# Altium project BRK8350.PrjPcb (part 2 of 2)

## Sheet Transceiver-M2.SchDoc: BRK8350 - M.2
size C; Author: Casey Smith; Organization: Opal Kelly; Address1: 13500 SW 72nd Ave STE 100; Address2: Portland, OR 97223; Address3: 217.391.3724; Address4: http://www.opalkelly.com; DocumentNumber: xxx; Revision: 1; SheetNumber: 6; SheetTotal: 7
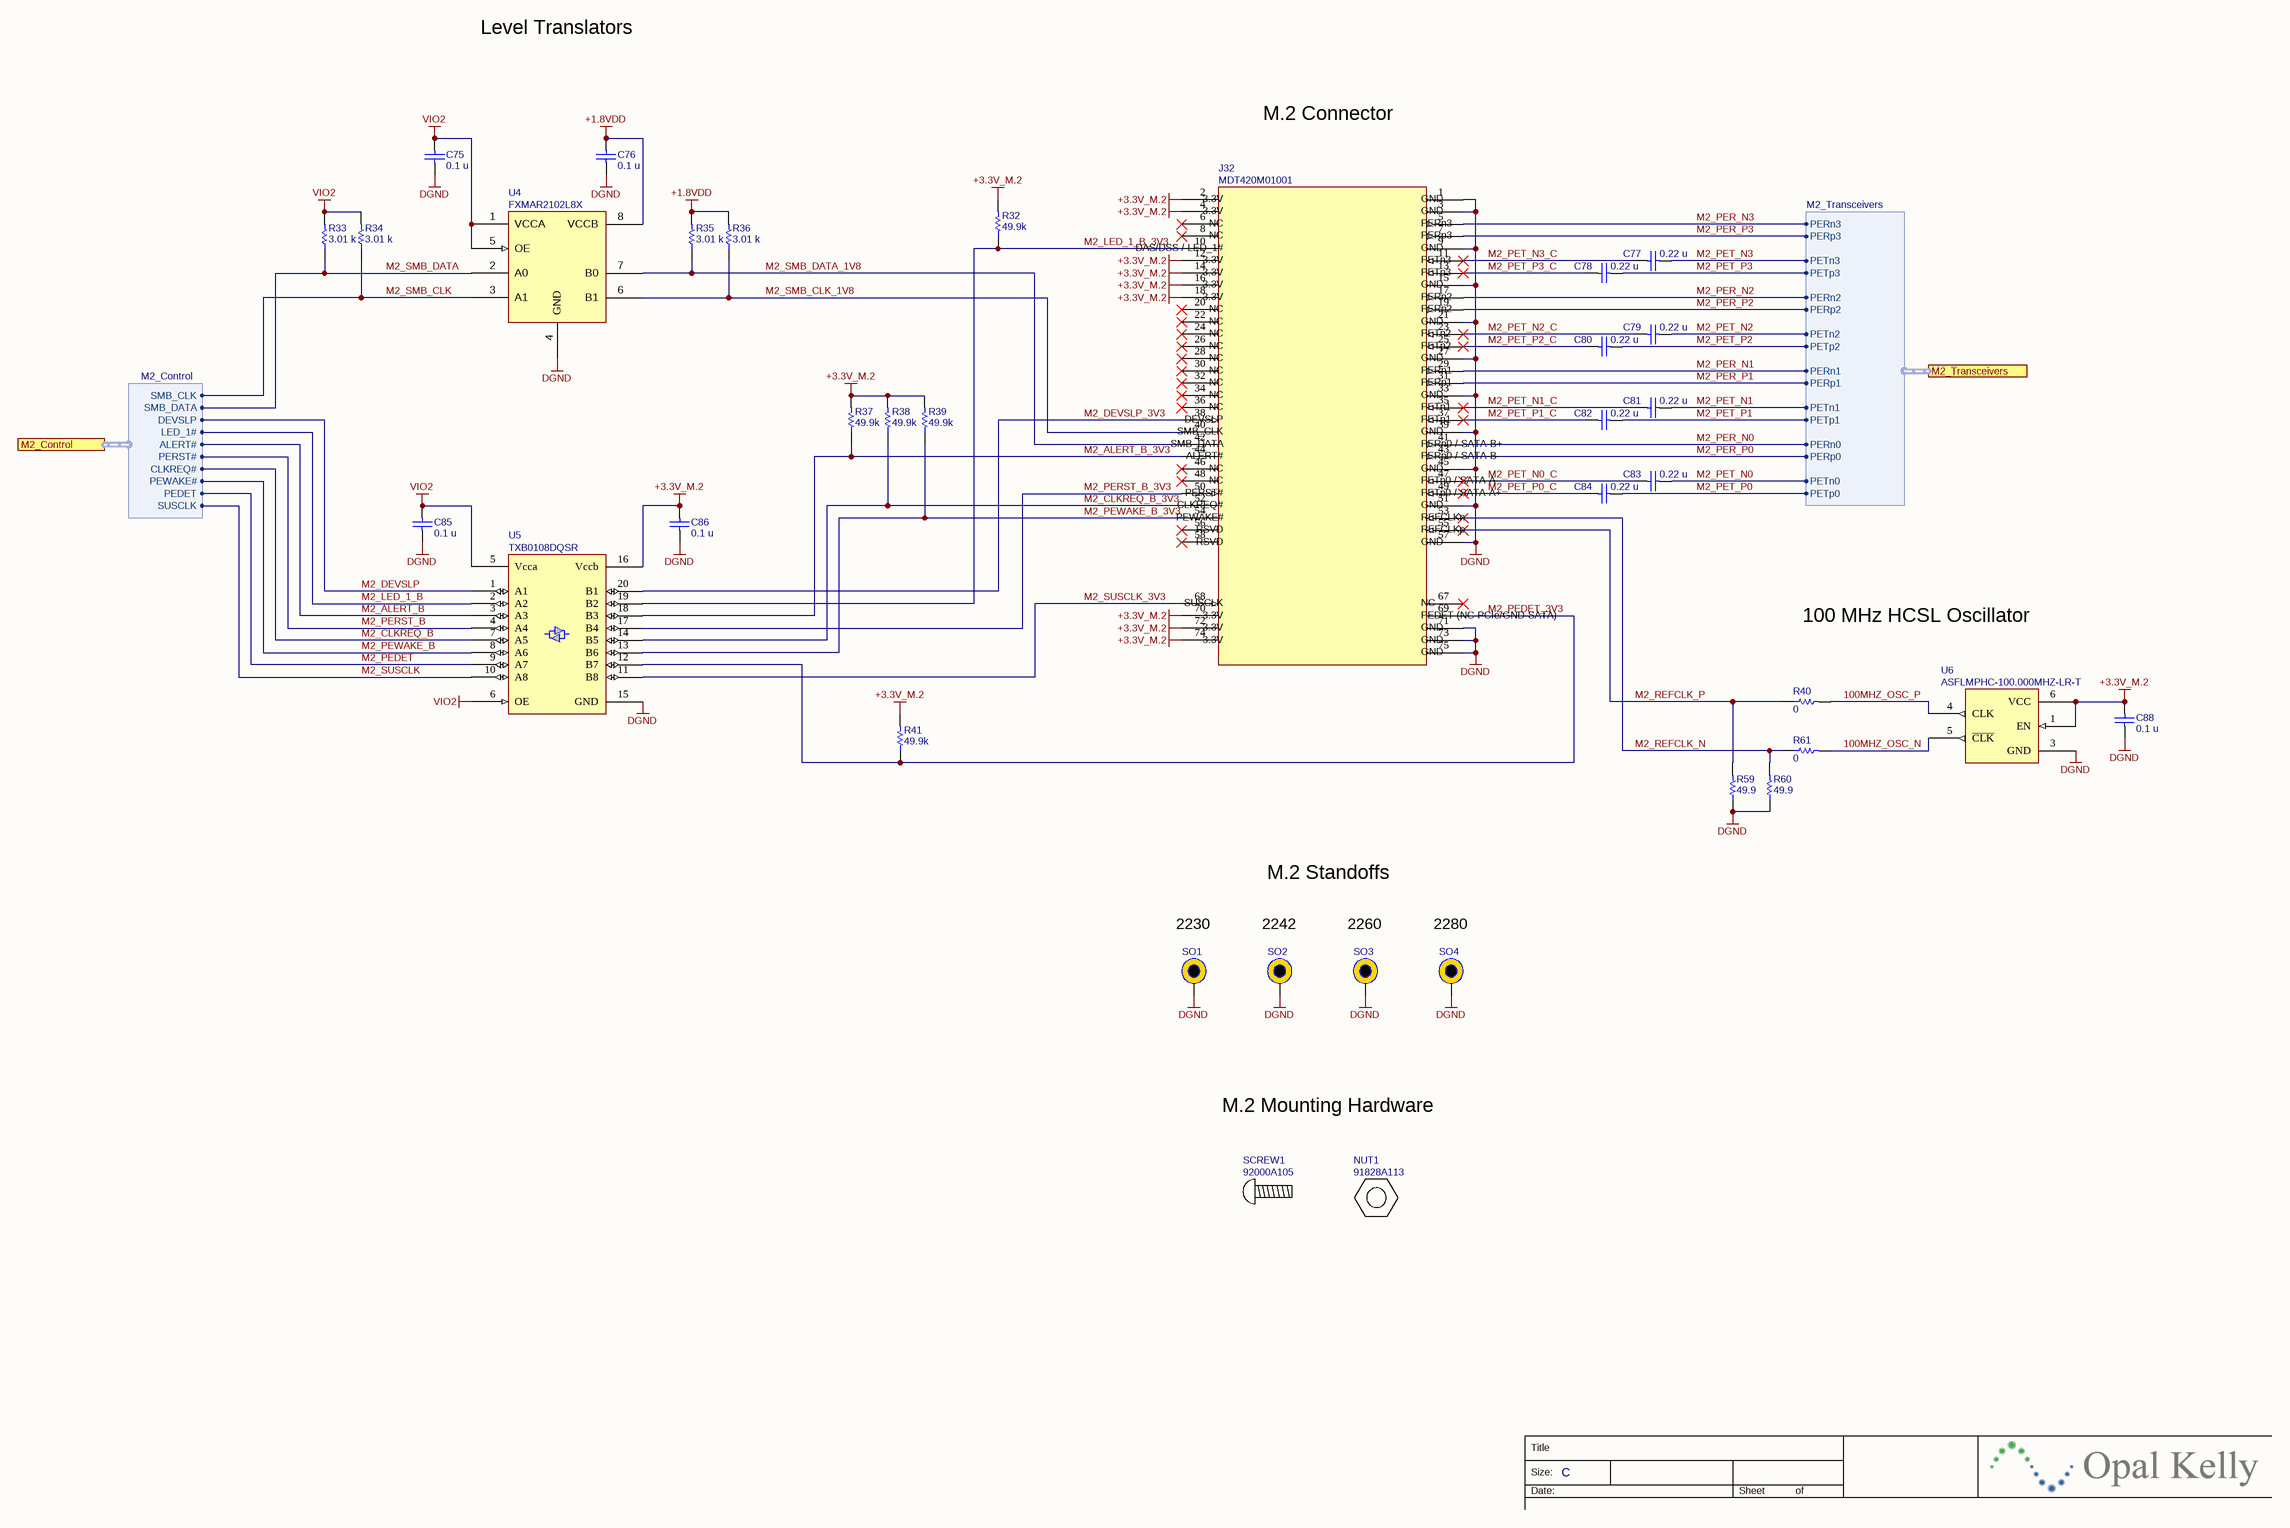
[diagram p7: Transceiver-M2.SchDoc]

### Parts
C75  value 0.1 u  [CAPC1005X06A]  (hidden comment: SM-0402, 10%, 10v)
C76  value 0.1 u  [CAPC1005X06A]  (hidden comment: SM-0402, 10%, 10v)
C77  value 0.22 u  [CAPC1005X06A]  (hidden comment: SM-0402, 10%, 10V, X5R)
C78  value 0.22 u  [CAPC1005X06A]  (hidden comment: SM-0402, 10%, 10V, X5R)
C79  value 0.22 u  [CAPC1005X06A]  (hidden comment: SM-0402, 10%, 10V, X5R)
C80  value 0.22 u  [CAPC1005X06A]  (hidden comment: SM-0402, 10%, 10V, X5R)
C81  value 0.22 u  [CAPC1005X06A]  (hidden comment: SM-0402, 10%, 10V, X5R)
C82  value 0.22 u  [CAPC1005X06A]  (hidden comment: SM-0402, 10%, 10V, X5R)
C83  value 0.22 u  [CAPC1005X06A]  (hidden comment: SM-0402, 10%, 10V, X5R)
C84  value 0.22 u  [CAPC1005X06A]  (hidden comment: SM-0402, 10%, 10V, X5R)
C85  value 0.1 u  [CAPC1005X06A]  (hidden comment: SM-0402, 10%, 10v)
C86  value 0.1 u  [CAPC1005X06A]  (hidden comment: SM-0402, 10%, 10v)
C88  value 0.1 u  [CAPC1005X06A]  (hidden comment: SM-0402, 10%, 10v)
J32  MDT420M01001  [M2-Connector_M-Keying]
NUT1  91828A113  (mechanical)
R32  value 49.9k  [RESC1005X06A]  (hidden comment: SM-0402, 1%, 1/16W)
R33  value 3.01 k  [RESC1005X06A]  (hidden comment: SM-0402, 1%, 1/16W)
R34  value 3.01 k  [RESC1005X06A]  (hidden comment: SM-0402, 1%, 1/16W)
R35  value 3.01 k  [RESC1005X06A]  (hidden comment: SM-0402, 1%, 1/16W)
R36  value 3.01 k  [RESC1005X06A]  (hidden comment: SM-0402, 1%, 1/16W)
R37  value 49.9k  [RESC1005X06A]  (hidden comment: SM-0402, 1%, 1/16W)
R38  value 49.9k  [RESC1005X06A]  (hidden comment: SM-0402, 1%, 1/16W)
R39  value 49.9k  [RESC1005X06A]  (hidden comment: SM-0402, 1%, 1/16W)
R40  value 0  [RESC1005X06A]  (hidden comment: SM-0402, 1%, 1/16W)
R41  value 49.9k  [RESC1005X06A]  (hidden comment: SM-0402, 1%, 1/16W)
R59  value 49.9  [RESC1005X06A]  (hidden comment: SM-0402, 1%, 1/16W)
R60  value 49.9  [RESC1005X06A]  (hidden comment: SM-0402, 1%, 1/16W)
R61  value 0  [RESC1005X06A]  (hidden comment: SM-0402, 1%, 1/16W)
SCREW1  92000A105  (mechanical)
SO1  Standoff  [9774025151R-NO-PASTE]  (value not drawn)
SO2  Standoff  [9774025151R-NO-PASTE]  (value not drawn)
SO3  Standoff  [9774025151R-NO-PASTE]  (value not drawn)
SO4  Standoff  [9774025151R-NO-PASTE]  (value not drawn)
U4  FXMAR2102L8X  [FXMAR2102L8X]
U5  TXB0108DQSR  [TXB0108DQSR]
U6  ASFLMPHC-100.000MHZ-LR-T  [OSC_SMD_5x32]

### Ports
M2_Control (harness M2_Control), M2_Transceivers (harness M2_Transceivers)

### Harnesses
M2_Control: DEVSLP, SMB_CLK, SMB_DATA, ALERT#, PERST#, CLKREQ#, PEWAKE#, LED_1#, SUSCLK, PEDET
M2_Transceivers: PETn3, PETp3, PERn3, PERp3, PETn2, PETp2, PERn2, PERp2, PETn1, PETp1, PERn1, PERp1, PETn0, PETp0, PERn0, PERp0

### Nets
+1.8VDD: C76.2 R35.2 R36.2 U4.8(VCCB)
+3.3V_M.2: C86.2 C88.2 J32.2 J32.4 J32.12 J32.14 J32.16 J32.18 J32.70 J32.72 J32.74 R32.2 R37.2 R38.2 R39.2 R41.2 U5.16(Vccb) U6.1(EN) U6.6(VCC)
DGND: C75.1 C76.1 C85.1 C86.1 C88.1 J32.1 J32.3 J32.9 J32.15 J32.21 J32.27 J32.33 J32.39 J32.45 J32.51 J32.57 J32.71 J32.73 J32.75 R59.1 R60.1 SO1.1 SO2.1 SO3.1 SO4.1 U4.4(GND) U5.15(GND) U6.3(GND)
VIO2: C75.2 C85.2 R33.2 R34.2 U4.1(VCCA) U4.5(OE) U5.5(Vcca) U5.6(OE)
100MHZ_OSC_N: R61.2 U6.5(~{CLK})
100MHZ_OSC_P: R40.2 U6.4(CLK)
M2_ALERT_B: U5.3(A3) ; port M2_Control.ALERT#
M2_ALERT_B_3V3: J32.44 R37.1 U5.18(B3)
M2_CLKREQ_B: U5.7(A5) ; port M2_Control.CLKREQ#
M2_CLKREQ_B_3V3: J32.52 R38.1 U5.14(B5)
M2_DEVSLP: U5.1(A1) ; port M2_Control.DEVSLP
M2_DEVSLP_3V3: J32.38 U5.20(B1)
M2_LED_1_B: U5.2(A2) ; port M2_Control.LED_1#
M2_LED_1_B_3V3: J32.10 R32.1 U5.19(B2)
M2_PEDET: U5.9(A7) ; port M2_Control.PEDET
M2_PEDET_3V3: J32.69 R41.1 U5.12(B7)
M2_PER_N0: J32.41 ; port M2_Transceivers.PERn0
M2_PER_N1: J32.29 ; port M2_Transceivers.PERn1
M2_PER_N2: J32.17 ; port M2_Transceivers.PERn2
M2_PER_N3: J32.5 ; port M2_Transceivers.PERn3
M2_PER_P0: J32.43 ; port M2_Transceivers.PERp0
M2_PER_P1: J32.31 ; port M2_Transceivers.PERp1
M2_PER_P2: J32.19 ; port M2_Transceivers.PERp2
M2_PER_P3: J32.7 ; port M2_Transceivers.PERp3
M2_PERST_B: U5.4(A4) ; port M2_Control.PERST#
M2_PERST_B_3V3: J32.50 U5.17(B4)
M2_PET_N0: C83.1 ; port M2_Transceivers.PETn0
M2_PET_N0_C: C83.2 J32.47
M2_PET_N1: C81.1 ; port M2_Transceivers.PETn1
M2_PET_N1_C: C81.2 J32.35
M2_PET_N2: C79.1 ; port M2_Transceivers.PETn2
M2_PET_N2_C: C79.2 J32.23
M2_PET_N3: C77.1 ; port M2_Transceivers.PETn3
M2_PET_N3_C: C77.2 J32.11
M2_PET_P0: C84.1 ; port M2_Transceivers.PETp0
M2_PET_P0_C: C84.2 J32.49
M2_PET_P1: C82.1 ; port M2_Transceivers.PETp1
M2_PET_P1_C: C82.2 J32.37
M2_PET_P2: C80.1 ; port M2_Transceivers.PETp2
M2_PET_P2_C: C80.2 J32.25
M2_PET_P3: C78.1 ; port M2_Transceivers.PETp3
M2_PET_P3_C: C78.2 J32.13
M2_PEWAKE_B: U5.8(A6) ; port M2_Control.PEWAKE#
M2_PEWAKE_B_3V3: J32.54 R39.1 U5.13(B6)
M2_REFCLK_N: J32.53 R60.2 R61.1
M2_REFCLK_P: J32.55 R40.1 R59.2
M2_SMB_CLK: R34.1 U4.3(A1) ; port M2_Control.SMB_CLK
M2_SMB_CLK_1V8: J32.40 R36.1 U4.6(B1)
M2_SMB_DATA: R33.1 U4.2(A0) ; port M2_Control.SMB_DATA
M2_SMB_DATA_1V8: J32.42 R35.1 U4.7(B0)
M2_SUSCLK: U5.10(A8) ; port M2_Control.SUSCLK
M2_SUSCLK_3V3: J32.68 U5.11(B8)

Not connected (* = marked no-connect by the designer): J32 6* 8* 20* 22* 24* 26* 28* 30* 32* 34* 36* 46* 48* 56* 58* 67*

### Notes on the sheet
- Level Translators
- M.2 Connector
- 100 MHz HCSL Oscillator
- M.2 Standoffs
- 2230
- 2242
- 2260
- 2280
- M.2 Mounting Hardware
- Title
- Size:
- Date:
- C
- Sheet
- of

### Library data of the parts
C75 C76 C85 C86 C88 = 000070: Partnumber: 000070; manufacturer: Kemet; manufacturer_pn: C0402C104K8PACTU; ValueFloat: 1E-7; id: 750; inventory_price: 0.0023; reorder_quantity: 70000; x_tolerance: 10
C77-C84 = 000333: Partnumber: 000333; manufacturer: Taiyo Yuden; manufacturer_pn: LMK105BJ224KV-F; ValueFloat: 2.2E-7; id: 3750; inventory_price: 0.0056; reorder_quantity: 10000; x_tolerance: 10
J32 = 001722: Partnumber: 001722; manufacturer: Amphenol; id: 221876; inventory_price: 0.75
NUT1 = NUT: M2.5 hex nut; Manufacturer: McMaster-Carr; partnumber: 001810
R32 R37-R39 R41 = 001035: Partnumber: 001035; manufacturer: Vishay; manufacturer_pn: CRCW040249K9FKED; ValueFloat: 49900; id: 26623; inventory_price: 0.0015; x_tolerance: 1
R33-R36 = 001126: Partnumber: 001126; manufacturer: Vishay; manufacturer_pn: CRCW04023K01FKED; ValueFloat: 3010; id: 35682; inventory_price: 0.015; x_tolerance: 1
R40 R61 = 001713: Partnumber: 001713; manufacturer: Vishay; manufacturer_pn: CRCW04020000Z0EDC; id: 219362; inventory_price: 0.004; reorder_quantity: 20000; x_tolerance: 1
R59 R60 = 001715: Partnumber: 001715; manufacturer: Vishay; manufacturer_pn: CRCW040249R9FKEDC; id: 219364; inventory_price: 0.005; reorder_quantity: 1000; x_tolerance: 1
SCREW1 = SCREW: Metric Pan Head Phil Machine Screw; Manufacturer: McMaster-Carr; partnumber: 001811
SO1-SO4 = 9774025151R: SMT steel standoff, M2.5 threads, 2.5 mm stack height; Manufacturer: Wurth; partnumber: 001726
U4 = 001559: Partnumber: 001559; manufacturer: ON Semiconductor; id: 168047; inventory_price: 0.3
U5 = 001324: Partnumber: 001324; manufacturer: Texas Instruments; id: 94563; inventory_price: 1.67
U6 = 001804: Partnumber: 001804; manufacturer: Abracon; id: 273756; inventory_price: 2.65

## Sheet MC3-Transceiver.SchDoc: BRK8350 - Mezzanine Connector MC3
size C; Author: Casey Smith; Organization: Opal Kelly; Address1: 13500 SW 72nd Ave STE 100; Address2: Portland, OR 97223; Address3: 217.391.3724; Address4: http://www.opalkelly.com; DocumentNumber: xxx; Revision: 1; SheetNumber: 4; SheetTotal: 7
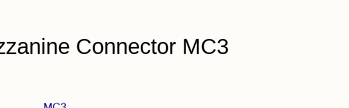
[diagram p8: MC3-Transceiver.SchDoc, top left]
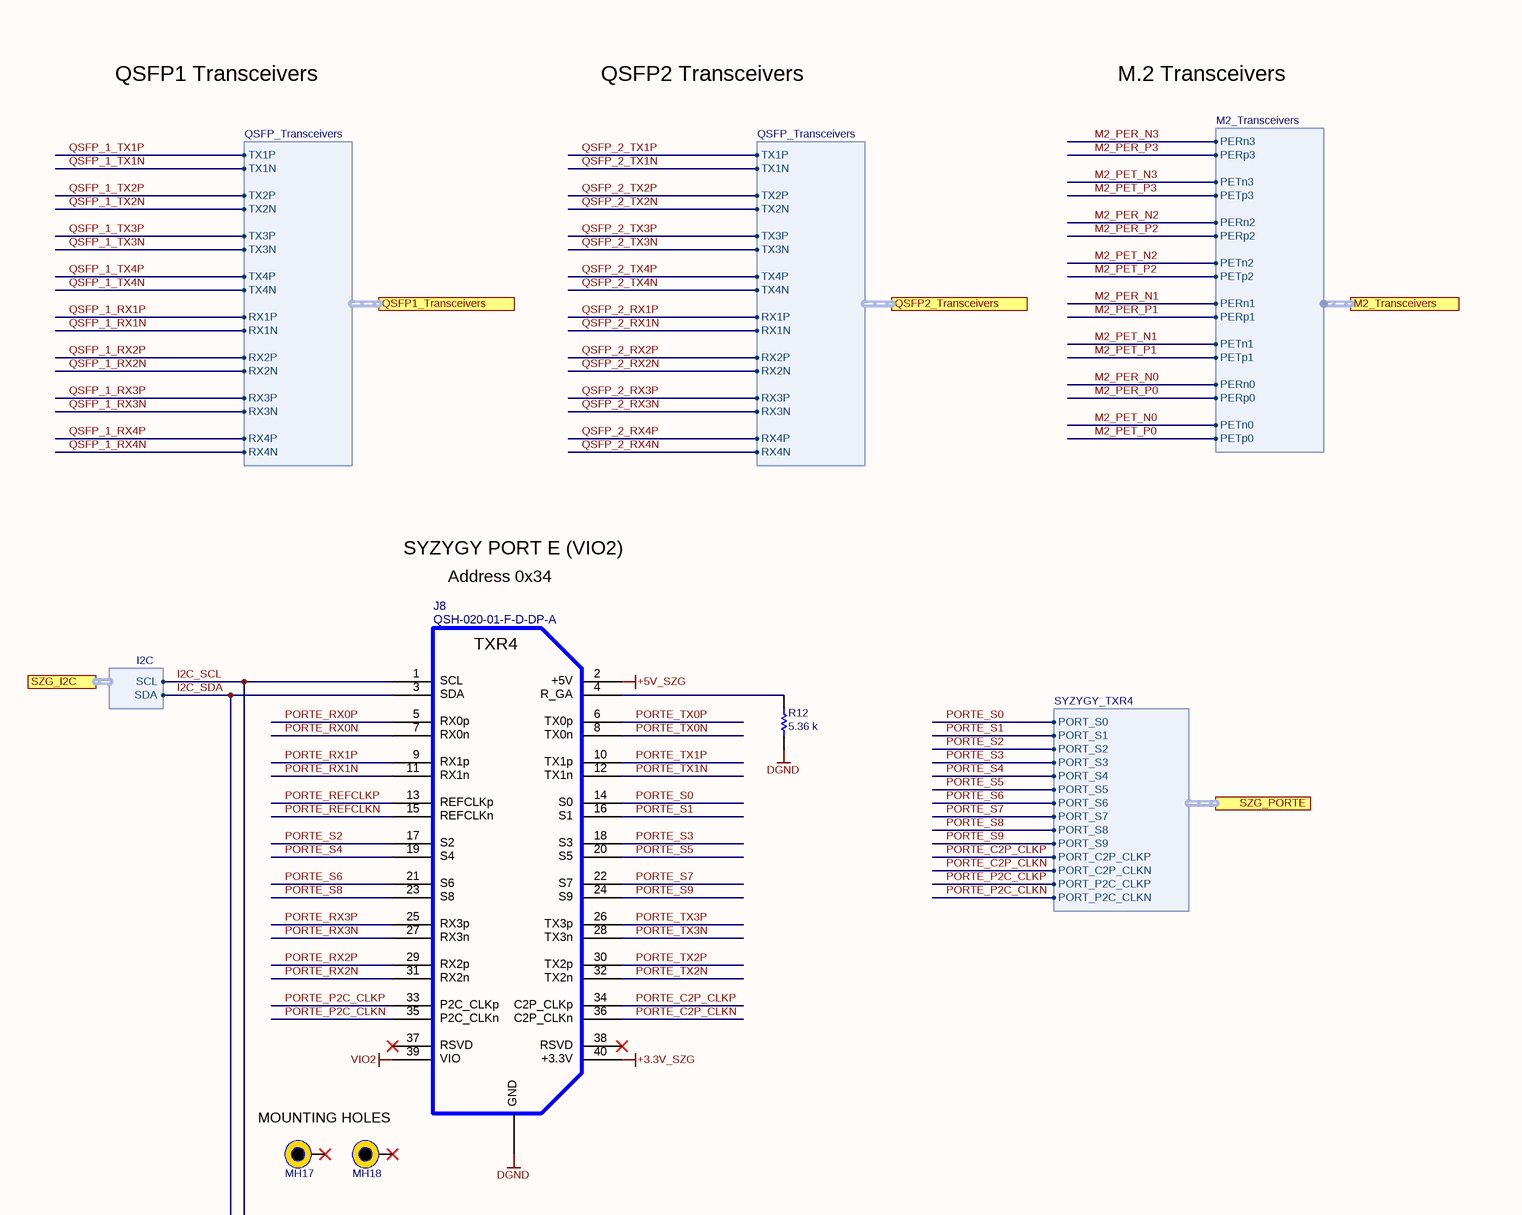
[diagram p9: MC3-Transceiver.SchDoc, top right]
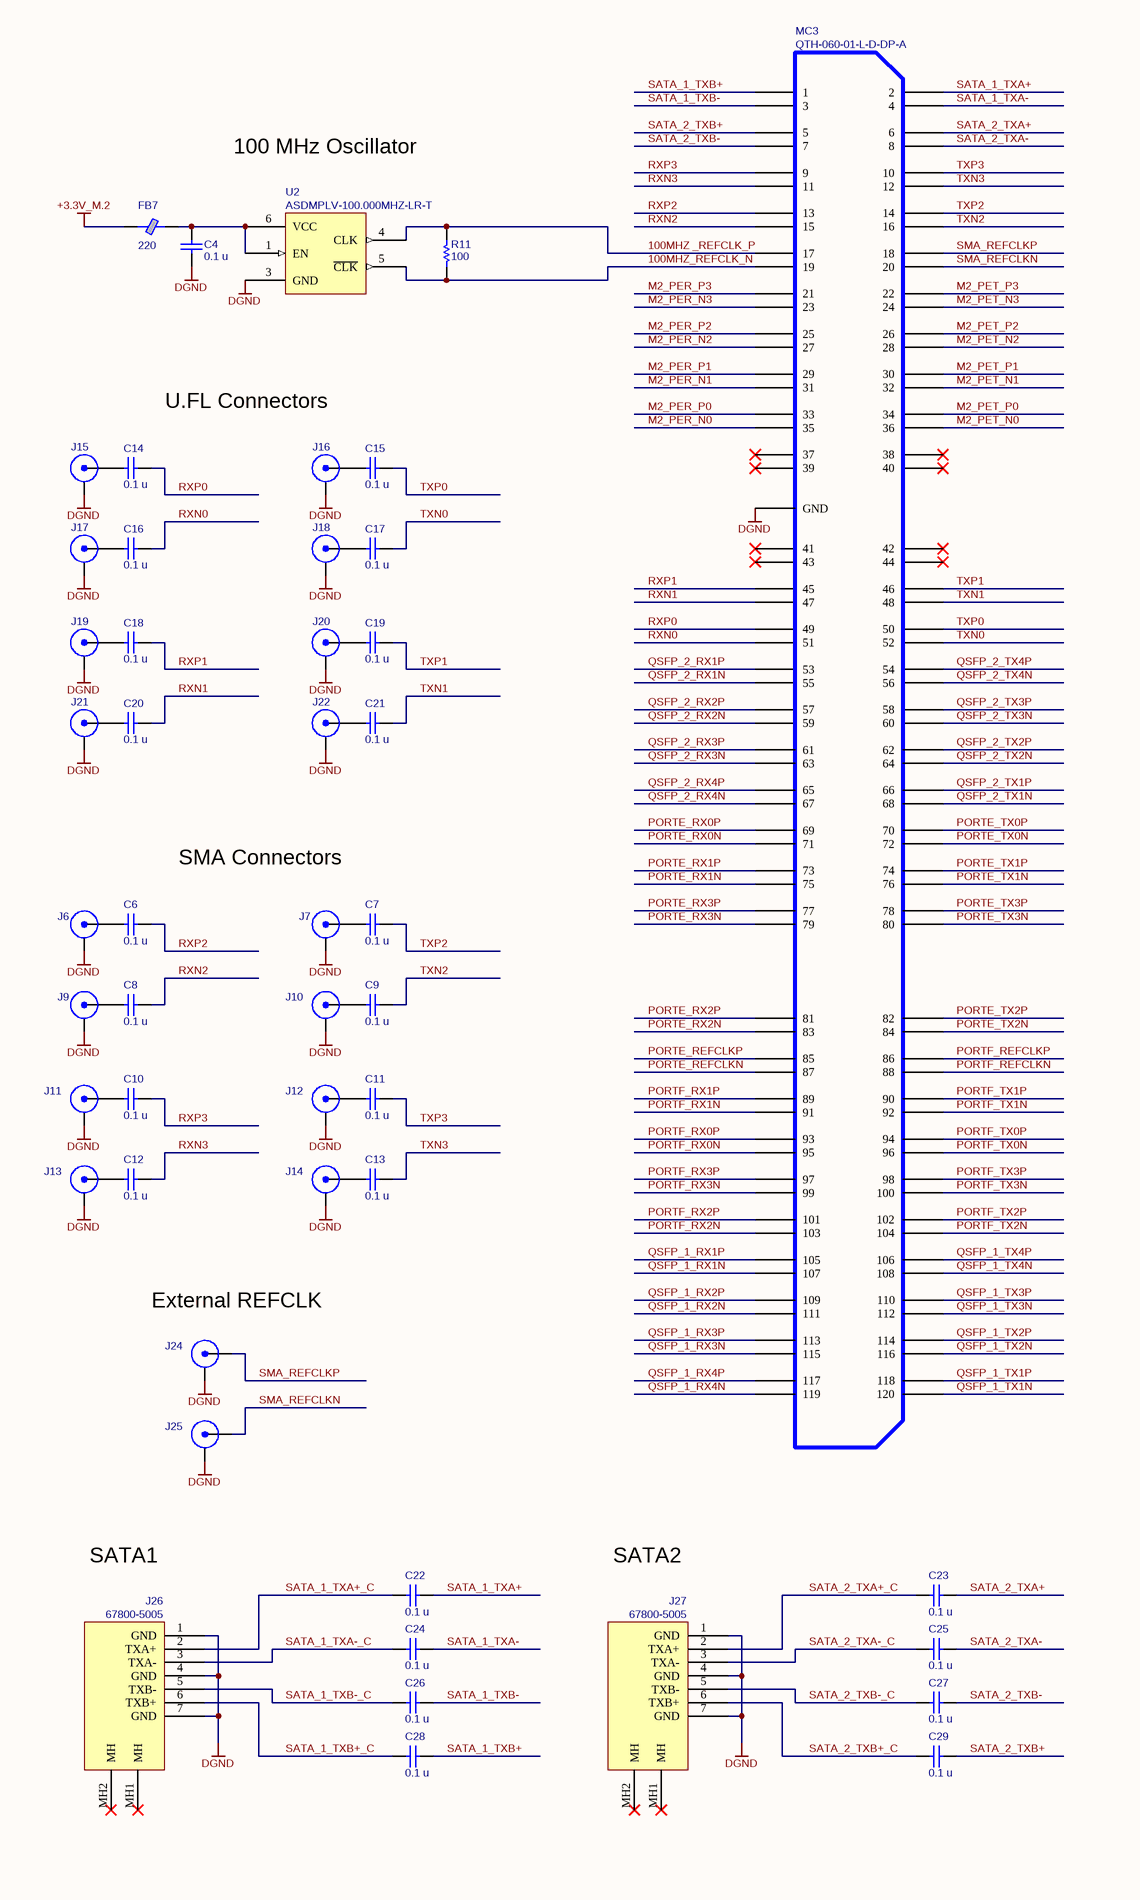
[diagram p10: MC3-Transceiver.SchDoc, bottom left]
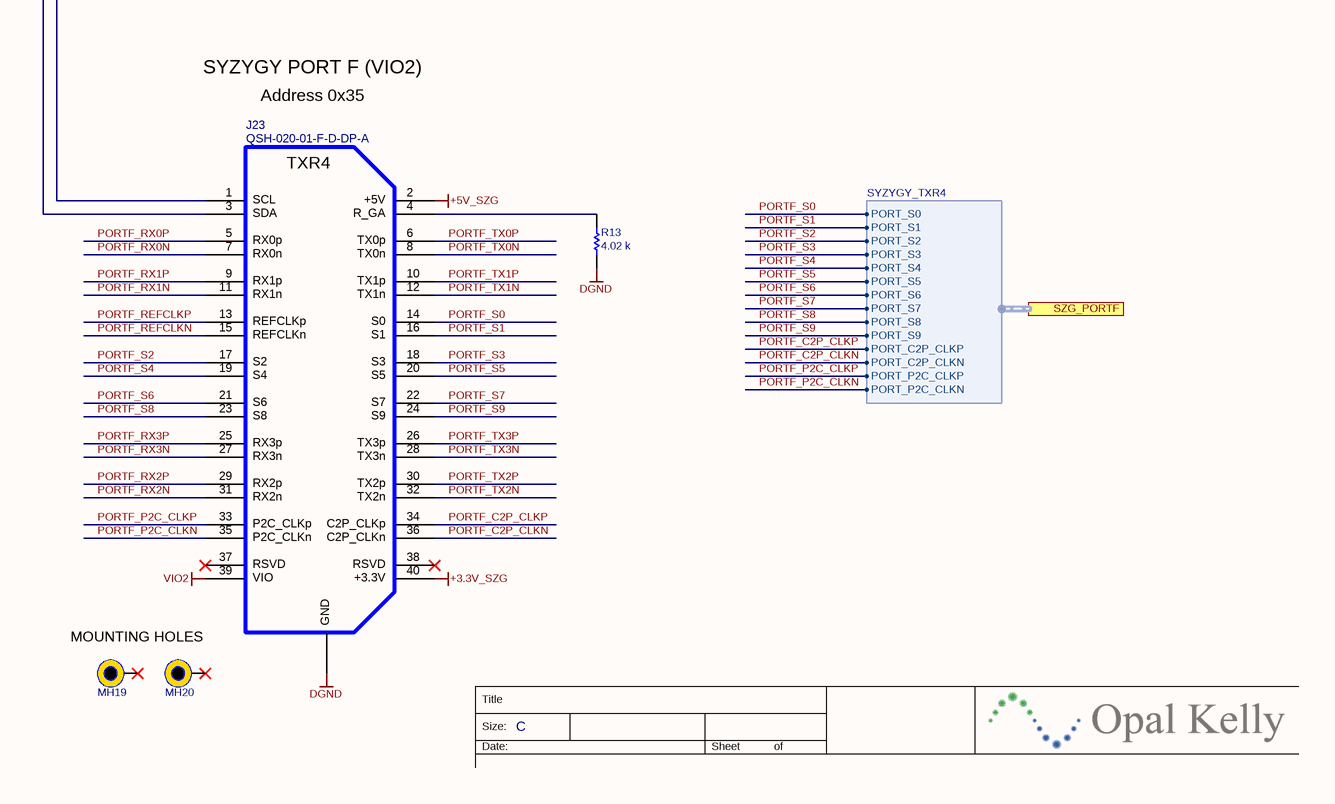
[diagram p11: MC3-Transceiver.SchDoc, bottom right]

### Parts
C4  value 0.1 u  [CAPC1005X06A]  (hidden comment: SM-0402, 10%, 10v)
C6  value 0.1 u  [CAPC1005X06A]  (hidden comment: SM-0402, 10%, 10v)
C7  value 0.1 u  [CAPC1005X06A]  (hidden comment: SM-0402, 10%, 10v)
C8  value 0.1 u  [CAPC1005X06A]  (hidden comment: SM-0402, 10%, 10v)
C9  value 0.1 u  [CAPC1005X06A]  (hidden comment: SM-0402, 10%, 10v)
C10  value 0.1 u  [CAPC1005X06A]  (hidden comment: SM-0402, 10%, 10v)
C11  value 0.1 u  [CAPC1005X06A]  (hidden comment: SM-0402, 10%, 10v)
C12  value 0.1 u  [CAPC1005X06A]  (hidden comment: SM-0402, 10%, 10v)
C13  value 0.1 u  [CAPC1005X06A]  (hidden comment: SM-0402, 10%, 10v)
C14  value 0.1 u  [CAPC1005X06A]  (hidden comment: SM-0402, 10%, 10v)
C15  value 0.1 u  [CAPC1005X06A]  (hidden comment: SM-0402, 10%, 10v)
C16  value 0.1 u  [CAPC1005X06A]  (hidden comment: SM-0402, 10%, 10v)
C17  value 0.1 u  [CAPC1005X06A]  (hidden comment: SM-0402, 10%, 10v)
C18  value 0.1 u  [CAPC1005X06A]  (hidden comment: SM-0402, 10%, 10v)
C19  value 0.1 u  [CAPC1005X06A]  (hidden comment: SM-0402, 10%, 10v)
C20  value 0.1 u  [CAPC1005X06A]  (hidden comment: SM-0402, 10%, 10v)
C21  value 0.1 u  [CAPC1005X06A]  (hidden comment: SM-0402, 10%, 10v)
C22  value 0.1 u  [CAPC1005X06A]  (hidden comment: SM-0402, 10%, 10v)
C23  value 0.1 u  [CAPC1005X06A]  (hidden comment: SM-0402, 10%, 10v)
C24  value 0.1 u  [CAPC1005X06A]  (hidden comment: SM-0402, 10%, 10v)
C25  value 0.1 u  [CAPC1005X06A]  (hidden comment: SM-0402, 10%, 10v)
C26  value 0.1 u  [CAPC1005X06A]  (hidden comment: SM-0402, 10%, 10v)
C27  value 0.1 u  [CAPC1005X06A]  (hidden comment: SM-0402, 10%, 10v)
C28  value 0.1 u  [CAPC1005X06A]  (hidden comment: SM-0402, 10%, 10v)
C29  value 0.1 u  [CAPC1005X06A]  (hidden comment: SM-0402, 10%, 10v)
FB7  value 220  [RESC2012N]  (hidden comment: 220 OHM 2000MA 0805)
J6  RXP2  [SMA]  (value not drawn)
J7  TXP2  [SMA]  (value not drawn)
J8  QSH-020-01-F-D-DP-A  [QSH-020-01-X-D-DP-A-L]
J9  RXN2  [SMA]  (value not drawn)
J10  TXN2  [SMA]  (value not drawn)
J11  RXP3  [SMA]  (value not drawn)
J12  TXP3  [SMA]  (value not drawn)
J13  RXN3  [SMA]  (value not drawn)
J14  TXN3  [SMA]  (value not drawn)
J15  RXP0  [UFL-R-SMT-1]  (value not drawn)
J16  TXP0  [UFL-R-SMT-1]  (value not drawn)
J17  RXN0  [UFL-R-SMT-1]  (value not drawn)
J18  TXN0  [UFL-R-SMT-1]  (value not drawn)
J19  RXP1  [UFL-R-SMT-1]  (value not drawn)
J20  TXP1  [UFL-R-SMT-1]  (value not drawn)
J21  RXN1  [UFL-R-SMT-1]  (value not drawn)
J22  TXN1  [UFL-R-SMT-1]  (value not drawn)
J23  QSH-020-01-F-D-DP-A  [QSH-020-01-X-D-DP-A-L]
J24  REFCLKP  [SMA]  (value not drawn)
J25  REFCLKN  [SMA]  (value not drawn)
J26  67800-5005  [MOLEX-67800-5005]
J27  67800-5005  [MOLEX-67800-5005]
MC3  QTH-060-01-L-D-DP-A  [QTH-060-01-X-D-DP-A]
MH17  MTG  [MTG-3.2/6.5-PTH]  (value not drawn)
MH18  MTG  [MTG-3.2/6.5-PTH]  (value not drawn)
MH19  MTG  [MTG-3.2/6.5-PTH]  (value not drawn)
MH20  MTG  [MTG-3.2/6.5-PTH]  (value not drawn)
R11  value 100  [RESC1005X06A]  (hidden comment: SM-0402, 1%, 1/16W)
R12  value 5.36 k  [RESC1005X06A]  (hidden comment: RC0402FR-075K36L)
R13  value 4.02 k  [RESC1005X06A]  (hidden comment: CRCW04024K02FKED)
U2  ASDMPLV-100.000MHZ-LR-T  [OSC_SMD_25x20]

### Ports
M2_Transceivers (harness M2_Transceivers), QSFP1_Transceivers (harness QSFP_Transceivers), QSFP2_Transceivers (harness QSFP_Transceivers), SZG_I2C (harness I2C), SZG_PORTE (harness SYZYGY_TXR4), SZG_PORTF (harness SYZYGY_TXR4)

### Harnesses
QSFP_Transceivers: TX1P, TX1N, TX2P, TX2N, TX3P, TX3N, TX4P, TX4N, RX1P, RX1N, RX2P, RX2N, RX3P, RX3N, RX4P, RX4N
I2C: SCL, SDA
SYZYGY_TXR4: PORT_S0, PORT_S1, PORT_S2, PORT_S3, PORT_S4, PORT_S5, PORT_S6, PORT_S7, PORT_S8, PORT_S9, PORT_C2P_CLKP, PORT_C2P_CLKN, PORT_P2C_CLKP, PORT_P2C_CLKN
M2_Transceivers: PETn3, PETp3, PERn3, PERp3, PETn2, PETp2, PERn2, PERp2, PETn1, PETp1, PERn1, PERp1, PETn0, PETp0, PERn0, PERp0

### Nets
+3.3V_M.2: FB7.1
+3.3V_SZG: J8.40 J23.40
+5V_SZG: J8.2 J23.2
DGND: C4.1 J6.2(GND) J7.2(GND) J8.0(GND) J9.2(GND) J10.2(GND) J11.2(GND) J12.2(GND) J13.2(GND) J14.2(GND) J15.2(GND) J16.2(GND) J17.2(GND) J18.2(GND) J19.2(GND) J20.2(GND) J21.2(GND) J22.2(GND) J23.0(GND) J24.2(GND) J25.2(GND) J26.1(GND) J26.4(GND) J26.7(GND) J27.1(GND) J27.4(GND) J27.7(GND) MC3.0(GND) R12.1 R13.1 U2.3(GND)
VIO2: J8.39 J23.39
100MHZ _REFCLK_P: MC3.17 R11.2 U2.4(CLK)
100MHZ_REFCLK_N: MC3.19 R11.1 U2.5(~{CLK})
I2C_SCL: J8.1 J23.1 ; port SZG_I2C.SCL
I2C_SDA: J8.3 J23.3 ; port SZG_I2C.SDA
M2_PER_N0: MC3.35 ; port M2_Transceivers.PERn0
M2_PER_N1: MC3.31 ; port M2_Transceivers.PERn1
M2_PER_N2: MC3.27 ; port M2_Transceivers.PERn2
M2_PER_N3: MC3.23 ; port M2_Transceivers.PERn3
M2_PER_P0: MC3.33 ; port M2_Transceivers.PERp0
M2_PER_P1: MC3.29 ; port M2_Transceivers.PERp1
M2_PER_P2: MC3.25 ; port M2_Transceivers.PERp2
M2_PER_P3: MC3.21 ; port M2_Transceivers.PERp3
M2_PET_N0: MC3.36 ; port M2_Transceivers.PETn0
M2_PET_N1: MC3.32 ; port M2_Transceivers.PETn1
M2_PET_N2: MC3.28 ; port M2_Transceivers.PETn2
M2_PET_N3: MC3.24 ; port M2_Transceivers.PETn3
M2_PET_P0: MC3.34 ; port M2_Transceivers.PETp0
M2_PET_P1: MC3.30 ; port M2_Transceivers.PETp1
M2_PET_P2: MC3.26 ; port M2_Transceivers.PETp2
M2_PET_P3: MC3.22 ; port M2_Transceivers.PETp3
PORTE_C2P_CLKN: J8.36 ; port SZG_PORTE.PORT_C2P_CLKN
PORTE_C2P_CLKP: J8.34 ; port SZG_PORTE.PORT_C2P_CLKP
PORTE_P2C_CLKN: J8.35 ; port SZG_PORTE.PORT_P2C_CLKN
PORTE_P2C_CLKP: J8.33 ; port SZG_PORTE.PORT_P2C_CLKP
PORTE_REFCLKN: J8.15 MC3.87
PORTE_REFCLKP: J8.13 MC3.85
PORTE_RX0N: J8.7 MC3.71
PORTE_RX0P: J8.5 MC3.69
PORTE_RX1N: J8.11 MC3.75
PORTE_RX1P: J8.9 MC3.73
PORTE_RX2N: J8.31 MC3.83
PORTE_RX2P: J8.29 MC3.81
PORTE_RX3N: J8.27 MC3.79
PORTE_RX3P: J8.25 MC3.77
PORTE_S0: J8.14 ; port SZG_PORTE.PORT_S0
PORTE_S1: J8.16 ; port SZG_PORTE.PORT_S1
PORTE_S2: J8.17 ; port SZG_PORTE.PORT_S2
PORTE_S3: J8.18 ; port SZG_PORTE.PORT_S3
PORTE_S4: J8.19 ; port SZG_PORTE.PORT_S4
PORTE_S5: J8.20 ; port SZG_PORTE.PORT_S5
PORTE_S6: J8.21 ; port SZG_PORTE.PORT_S6
PORTE_S7: J8.22 ; port SZG_PORTE.PORT_S7
PORTE_S8: J8.23 ; port SZG_PORTE.PORT_S8
PORTE_S9: J8.24 ; port SZG_PORTE.PORT_S9
PORTE_TX0N: J8.8 MC3.72
PORTE_TX0P: J8.6 MC3.70
PORTE_TX1N: J8.12 MC3.76
PORTE_TX1P: J8.10 MC3.74
PORTE_TX2N: J8.32 MC3.84
PORTE_TX2P: J8.30 MC3.82
PORTE_TX3N: J8.28 MC3.80
PORTE_TX3P: J8.26 MC3.78
PORTF_C2P_CLKN: J23.36 ; port SZG_PORTF.PORT_C2P_CLKN
PORTF_C2P_CLKP: J23.34 ; port SZG_PORTF.PORT_C2P_CLKP
PORTF_P2C_CLKN: J23.35 ; port SZG_PORTF.PORT_P2C_CLKN
PORTF_P2C_CLKP: J23.33 ; port SZG_PORTF.PORT_P2C_CLKP
PORTF_REFCLKN: J23.15 MC3.88
PORTF_REFCLKP: J23.13 MC3.86
PORTF_RX0N: J23.7 MC3.95
PORTF_RX0P: J23.5 MC3.93
PORTF_RX1N: J23.11 MC3.91
PORTF_RX1P: J23.9 MC3.89
PORTF_RX2N: J23.31 MC3.103
PORTF_RX2P: J23.29 MC3.101
PORTF_RX3N: J23.27 MC3.99
PORTF_RX3P: J23.25 MC3.97
PORTF_S0: J23.14 ; port SZG_PORTF.PORT_S0
PORTF_S1: J23.16 ; port SZG_PORTF.PORT_S1
PORTF_S2: J23.17 ; port SZG_PORTF.PORT_S2
PORTF_S3: J23.18 ; port SZG_PORTF.PORT_S3
PORTF_S4: J23.19 ; port SZG_PORTF.PORT_S4
PORTF_S5: J23.20 ; port SZG_PORTF.PORT_S5
PORTF_S6: J23.21 ; port SZG_PORTF.PORT_S6
PORTF_S7: J23.22 ; port SZG_PORTF.PORT_S7
PORTF_S8: J23.23 ; port SZG_PORTF.PORT_S8
PORTF_S9: J23.24 ; port SZG_PORTF.PORT_S9
PORTF_TX0N: J23.8 MC3.96
PORTF_TX0P: J23.6 MC3.94
PORTF_TX1N: J23.12 MC3.92
PORTF_TX1P: J23.10 MC3.90
PORTF_TX2N: J23.32 MC3.104
PORTF_TX2P: J23.30 MC3.102
PORTF_TX3N: J23.28 MC3.100
PORTF_TX3P: J23.26 MC3.98
QSFP_1_RX1N: MC3.107 ; port QSFP1_Transceivers.RX1N
QSFP_1_RX1P: MC3.105 ; port QSFP1_Transceivers.RX1P
QSFP_1_RX2N: MC3.111 ; port QSFP1_Transceivers.RX2N
QSFP_1_RX2P: MC3.109 ; port QSFP1_Transceivers.RX2P
QSFP_1_RX3N: MC3.115 ; port QSFP1_Transceivers.RX3N
QSFP_1_RX3P: MC3.113 ; port QSFP1_Transceivers.RX3P
QSFP_1_RX4N: MC3.119 ; port QSFP1_Transceivers.RX4N
QSFP_1_RX4P: MC3.117 ; port QSFP1_Transceivers.RX4P
QSFP_1_TX1N: MC3.120 ; port QSFP1_Transceivers.TX1N
QSFP_1_TX1P: MC3.118 ; port QSFP1_Transceivers.TX1P
QSFP_1_TX2N: MC3.116 ; port QSFP1_Transceivers.TX2N
QSFP_1_TX2P: MC3.114 ; port QSFP1_Transceivers.TX2P
QSFP_1_TX3N: MC3.112 ; port QSFP1_Transceivers.TX3N
QSFP_1_TX3P: MC3.110 ; port QSFP1_Transceivers.TX3P
QSFP_1_TX4N: MC3.108 ; port QSFP1_Transceivers.TX4N
QSFP_1_TX4P: MC3.106 ; port QSFP1_Transceivers.TX4P
QSFP_2_RX1N: MC3.55 ; port QSFP2_Transceivers.RX1N
QSFP_2_RX1P: MC3.53 ; port QSFP2_Transceivers.RX1P
QSFP_2_RX2N: MC3.59 ; port QSFP2_Transceivers.RX2N
QSFP_2_RX2P: MC3.57 ; port QSFP2_Transceivers.RX2P
QSFP_2_RX3N: MC3.63 ; port QSFP2_Transceivers.RX3N
QSFP_2_RX3P: MC3.61 ; port QSFP2_Transceivers.RX3P
QSFP_2_RX4N: MC3.67 ; port QSFP2_Transceivers.RX4N
QSFP_2_RX4P: MC3.65 ; port QSFP2_Transceivers.RX4P
QSFP_2_TX1N: MC3.68 ; port QSFP2_Transceivers.TX1N
QSFP_2_TX1P: MC3.66 ; port QSFP2_Transceivers.TX1P
QSFP_2_TX2N: MC3.64 ; port QSFP2_Transceivers.TX2N
QSFP_2_TX2P: MC3.62 ; port QSFP2_Transceivers.TX2P
QSFP_2_TX3N: MC3.60 ; port QSFP2_Transceivers.TX3N
QSFP_2_TX3P: MC3.58 ; port QSFP2_Transceivers.TX3P
QSFP_2_TX4N: MC3.56 ; port QSFP2_Transceivers.TX4N
QSFP_2_TX4P: MC3.54 ; port QSFP2_Transceivers.TX4P
RXN0: C16.2 MC3.51
RXN1: C20.2 MC3.47
RXN2: C8.2 MC3.15
RXN3: C12.2 MC3.11
RXP0: C14.2 MC3.49
RXP1: C18.2 MC3.45
RXP2: C6.2 MC3.13
RXP3: C10.2 MC3.9
SATA_1_TXA+: C22.2 MC3.2
SATA_1_TXA+_C: C22.1 J26.2(TXA+)
SATA_1_TXA-: C24.2 MC3.4
SATA_1_TXA-_C: C24.1 J26.3(TXA-)
SATA_1_TXB+: C28.2 MC3.1
SATA_1_TXB+_C: C28.1 J26.6(TXB+)
SATA_1_TXB-: C26.2 MC3.3
SATA_1_TXB-_C: C26.1 J26.5(TXB-)
SATA_2_TXA+: C23.2 MC3.6
SATA_2_TXA+_C: C23.1 J27.2(TXA+)
SATA_2_TXA-: C25.2 MC3.8
SATA_2_TXA-_C: C25.1 J27.3(TXA-)
SATA_2_TXB+: C29.2 MC3.5
SATA_2_TXB+_C: C29.1 J27.6(TXB+)
SATA_2_TXB-: C27.2 MC3.7
SATA_2_TXB-_C: C27.1 J27.5(TXB-)
SMA_REFCLKN: J25.1(SIGNAL) MC3.20
SMA_REFCLKP: J24.1(SIGNAL) MC3.18
TXN0: C17.2 MC3.52
TXN1: C21.2 MC3.48
TXN2: C9.2 MC3.16
TXN3: C13.2 MC3.12
TXP0: C15.2 MC3.50
TXP1: C19.2 MC3.46
TXP2: C7.2 MC3.14
TXP3: C11.2 MC3.10
NetC4_2: C4.2 FB7.2 U2.1(EN) U2.6(VCC)
NetC6_1: C6.1 J6.1(SIGNAL)
NetC7_1: C7.1 J7.1(SIGNAL)
NetC8_1: C8.1 J9.1(SIGNAL)
NetC9_1: C9.1 J10.1(SIGNAL)
NetC10_1: C10.1 J11.1(SIGNAL)
NetC11_1: C11.1 J12.1(SIGNAL)
NetC12_1: C12.1 J13.1(SIGNAL)
NetC13_1: C13.1 J14.1(SIGNAL)
NetC14_1: C14.1 J15.1(SIGNAL)
NetC15_1: C15.1 J16.1(SIGNAL)
NetC16_1: C16.1 J17.1(SIGNAL)
NetC17_1: C17.1 J18.1(SIGNAL)
NetC18_1: C18.1 J19.1(SIGNAL)
NetC19_1: C19.1 J20.1(SIGNAL)
NetC20_1: C20.1 J21.1(SIGNAL)
NetC21_1: C21.1 J22.1(SIGNAL)
NetJ8_4: J8.4 R12.2
NetJ23_4: J23.4 R13.2

Not connected (* = marked no-connect by the designer): J8 37* 38*; J23 37* 38*; J26 MH1(MH)* MH2(MH)*; J27 MH1(MH)* MH2(MH)*; MC3 37* 38* 39* 40* 41* 42* 43* 44*; MH17 1*; MH18 1*; MH19 1*; MH20 1*

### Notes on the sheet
- Mezzanine Connector MC3
- QSFP1 Transceivers
- QSFP2 Transceivers
- M.2 Transceivers
- 100 MHz Oscillator
- U.FL Connectors
- Address 0x34
- SYZYGY PORT E (VIO2)
- SMA Connectors
- MOUNTING HOLES
- SYZYGY PORT F (VIO2)
- Address 0x35
- (near J24) External REFCLK
- SATA1
- SATA2
- Title
- Size:
- Date:
- C
- Sheet
- of

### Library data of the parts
C4 C6-C29 = 000070: as C75 on sheet Transceiver-M2
FB7 = 000783: Partnumber: 000783; manufacturer: Murata; manufacturer_pn: BLM21PG221SN1D; id: 12845; inventory_price: 0.02; reorder_quantity: 4000
J6 J7 J9-J14 J24 J25 = 000974: Straight SMA PCB Mount; Manufacturer: Amphenol; Manufacturer_PN: 901-144-8RFX; partnumber: 000974
J8 J23 = 000694: 0.5mm Double Row High Speed Socket Assembly; Partnumber: 000694; manufacturer: Samtec
J15-J22 = 001335: U.FL surface-mount coaxial connector; Manufacturer: Hirose; Manufacturer_PN: U.FL-R-SMT-1; partnumber: 001335; x_lifecycle_status: Production
J26 J27 = 000988: SATA 7-pin receptacle; Manufacturer: Molex; partnumber: 000988; Description 2: Vertical Mount, SMD, Latch, 15u Gold; x_lifecycle_status: Production
MC3 = 001769: Partnumber: 001769; manufacturer: Samtec
MH17-MH20 = MTG: Mounting hole; partnumber: ALIGNI_IGNORE
R11 = 000827: Partnumber: 000827; manufacturer: Vishay; manufacturer_pn: CRCW0402100RFKED; id: 13742; inventory_price: 0.0016; reorder_quantity: 2000; x_tolerance: 1
R12 = Resistor: Thick-film resistor; manufacturer: Yageo; partnumber: 001910; ValueFloat: 5360.0
R13 = Resistor: Thick-film resistor; manufacturer: Vishay; partnumber: 001007; ValueFloat: 4020.0
U2 = 001241: Partnumber: 001241; manufacturer: Abracon

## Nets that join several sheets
+1.8VDD: Top (TP7.1), MC1 (C1.2 J3.2 MC1.177 MC1.179), Transceiver-M2 (C76.2 R35.2 R36.2 U4.8)
+3.3V_M.2: Power (7 pins), Transceiver-M2 (19 pins), MC3-Transceiver (FB7.1)
+3.3V_QSFP: Transceiver-QSFP (20 pins), Power (7 pins)
+3.3V_SZG: MC2 (J4.40 J5.40), MC1 (J1.40 J2.40), Power (7 pins), MC3-Transceiver (J8.40 J23.40)
+3.3VDD: Top (TP4.1), MC1 (7 pins), Power (R30.2)
+5V_SZG: MC2 (J4.2 J5.2), MC1 (J1.2 J2.2), Power (7 pins), MC3-Transceiver (J8.2 J23.2)
+VDCIN: Top (TP2.1), MC1 (8 pins), Power (14 pins)
DGND: Top (TP10.1 TP13.1 TP15.1), Transceiver-QSFP (48 pins), MC2 (25 pins), MC1 (59 pins), Power (48 pins), Transceiver-M2 (28 pins), MC3-Transceiver (31 pins)
VCCBATT: Top (TP12.1), MC2 (MC2.6)
VIO1: Top (TP1.1), MC1 (J1.39 J2.39 MC1.174 MC1.176)
VIO2: Top (TP3.1), Transceiver-QSFP (18 pins), MC2 (J4.39 J5.39 MC2.2 MC2.4), Transceiver-M2 (8 pins), MC3-Transceiver (J8.39 J23.39)
VREF1: Top (TP6.1), MC1 (MC1.178)
VREF2: Top (TP9.1), MC2 (MC2.1)
I2C_SCL: MC2 (J4.1 J5.1), MC1 (J1.1 J2.1 MC1.12 U1.6), Power (U3.43), MC3-Transceiver (J8.1 J23.1)
I2C_SDA: MC2 (J4.3 J5.3), MC1 (J1.3 J2.3 MC1.10 U1.5), Power (U3.42), MC3-Transceiver (J8.3 J23.3)
M2_ALERT_B: MC2 (MC2.62), Transceiver-M2 (U5.3)
M2_CLKREQ_B: MC2 (MC2.63), Transceiver-M2 (U5.7)
M2_DEVSLP: MC2 (MC2.59), Transceiver-M2 (U5.1)
M2_LED_1_B: MC2 (MC2.60), Transceiver-M2 (U5.2)
M2_PEDET: MC2 (MC2.64), Transceiver-M2 (U5.9)
M2_PER_N0: Transceiver-M2 (J32.41), MC3-Transceiver (MC3.35)
M2_PER_N1: Transceiver-M2 (J32.29), MC3-Transceiver (MC3.31)
M2_PER_N2: Transceiver-M2 (J32.17), MC3-Transceiver (MC3.27)
M2_PER_N3: Transceiver-M2 (J32.5), MC3-Transceiver (MC3.23)
M2_PER_P0: Transceiver-M2 (J32.43), MC3-Transceiver (MC3.33)
M2_PER_P1: Transceiver-M2 (J32.31), MC3-Transceiver (MC3.29)
M2_PER_P2: Transceiver-M2 (J32.19), MC3-Transceiver (MC3.25)
M2_PER_P3: Transceiver-M2 (J32.7), MC3-Transceiver (MC3.21)
M2_PERST_B: MC2 (MC2.61), Transceiver-M2 (U5.4)
M2_PET_N0: Transceiver-M2 (C83.1), MC3-Transceiver (MC3.36)
M2_PET_N1: Transceiver-M2 (C81.1), MC3-Transceiver (MC3.32)
M2_PET_N2: Transceiver-M2 (C79.1), MC3-Transceiver (MC3.28)
M2_PET_N3: Transceiver-M2 (C77.1), MC3-Transceiver (MC3.24)
M2_PET_P0: Transceiver-M2 (C84.1), MC3-Transceiver (MC3.34)
M2_PET_P1: Transceiver-M2 (C82.1), MC3-Transceiver (MC3.30)
M2_PET_P2: Transceiver-M2 (C80.1), MC3-Transceiver (MC3.26)
M2_PET_P3: Transceiver-M2 (C78.1), MC3-Transceiver (MC3.22)
M2_PEWAKE_B: MC2 (MC2.65), Transceiver-M2 (U5.8)
M2_SMB_CLK: MC2 (MC2.57), Transceiver-M2 (R34.1 U4.3)
M2_SMB_DATA: MC2 (MC2.55), Transceiver-M2 (R33.1 U4.2)
M2_SUSCLK: MC2 (MC2.66), Transceiver-M2 (U5.10)
PORTE_C2P_CLKN: MC2 (MC2.156), MC3-Transceiver (J8.36)
PORTE_C2P_CLKP: MC2 (MC2.154), MC3-Transceiver (J8.34)
PORTE_P2C_CLKN: MC2 (MC2.150), MC3-Transceiver (J8.35)
PORTE_P2C_CLKP: MC2 (MC2.148), MC3-Transceiver (J8.33)
PORTE_S0: MC2 (MC2.137), MC3-Transceiver (J8.14)
PORTE_S1: MC2 (MC2.143), MC3-Transceiver (J8.16)
PORTE_S2: MC2 (MC2.140), MC3-Transceiver (J8.17)
PORTE_S3: MC2 (MC2.145), MC3-Transceiver (J8.18)
PORTE_S4: MC2 (MC2.138), MC3-Transceiver (J8.19)
PORTE_S5: MC2 (MC2.147), MC3-Transceiver (J8.20)
PORTE_S6: MC2 (MC2.136), MC3-Transceiver (J8.21)
PORTE_S7: MC2 (MC2.142), MC3-Transceiver (J8.22)
PORTE_S8: MC2 (MC2.153), MC3-Transceiver (J8.23)
PORTE_S9: MC2 (MC2.151), MC3-Transceiver (J8.24)
PORTF_C2P_CLKN: MC2 (MC2.171), MC3-Transceiver (J23.36)
PORTF_C2P_CLKP: MC2 (MC2.169), MC3-Transceiver (J23.34)
PORTF_P2C_CLKN: MC2 (MC2.164), MC3-Transceiver (J23.35)
PORTF_P2C_CLKP: MC2 (MC2.162), MC3-Transceiver (J23.33)
PORTF_S0: MC2 (MC2.180), MC3-Transceiver (J23.14)
PORTF_S1: MC2 (MC2.178), MC3-Transceiver (J23.16)
PORTF_S2: MC2 (MC2.160), MC3-Transceiver (J23.17)
PORTF_S3: MC2 (MC2.159), MC3-Transceiver (J23.18)
PORTF_S4: MC2 (MC2.158), MC3-Transceiver (J23.19)
PORTF_S5: MC2 (MC2.161), MC3-Transceiver (J23.20)
PORTF_S6: MC2 (MC2.170), MC3-Transceiver (J23.21)
PORTF_S7: MC2 (MC2.173), MC3-Transceiver (J23.22)
PORTF_S8: MC2 (MC2.172), MC3-Transceiver (J23.23)
PORTF_S9: MC2 (MC2.175), MC3-Transceiver (J23.24)
QSFP_1_INT_B: Transceiver-QSFP (R46.1 U8.3), MC2 (MC2.129)
QSFP_1_LP_MODE: Transceiver-QSFP (U7.10), MC2 (MC2.125)
QSFP_1_MODPRS_B: Transceiver-QSFP (U7.7), MC2 (MC2.126)
QSFP_1_MODSEL_B: Transceiver-QSFP (U7.9), MC2 (MC2.122)
QSFP_1_RESET_B: Transceiver-QSFP (U7.8), MC2 (MC2.124)
QSFP_1_RX1N: Transceiver-QSFP (J30.18), MC3-Transceiver (MC3.107)
QSFP_1_RX1P: Transceiver-QSFP (J30.17), MC3-Transceiver (MC3.105)
QSFP_1_RX2N: Transceiver-QSFP (J30.21), MC3-Transceiver (MC3.111)
QSFP_1_RX2P: Transceiver-QSFP (J30.22), MC3-Transceiver (MC3.109)
QSFP_1_RX3N: Transceiver-QSFP (J30.15), MC3-Transceiver (MC3.115)
QSFP_1_RX3P: Transceiver-QSFP (J30.14), MC3-Transceiver (MC3.113)
QSFP_1_RX4N: Transceiver-QSFP (J30.24), MC3-Transceiver (MC3.119)
QSFP_1_RX4P: Transceiver-QSFP (J30.25), MC3-Transceiver (MC3.117)
QSFP_1_SCL: Transceiver-QSFP (R49.1 U9.2), MC2 (MC2.123)
QSFP_1_SDA: Transceiver-QSFP (R50.1 U9.3), MC2 (MC2.121)
QSFP_1_TX1N: Transceiver-QSFP (J30.37), MC3-Transceiver (MC3.120)
QSFP_1_TX1P: Transceiver-QSFP (J30.36), MC3-Transceiver (MC3.118)
QSFP_1_TX2N: Transceiver-QSFP (J30.2), MC3-Transceiver (MC3.116)
QSFP_1_TX2P: Transceiver-QSFP (J30.3), MC3-Transceiver (MC3.114)
QSFP_1_TX3N: Transceiver-QSFP (J30.34), MC3-Transceiver (MC3.112)
QSFP_1_TX3P: Transceiver-QSFP (J30.33), MC3-Transceiver (MC3.110)
QSFP_1_TX4N: Transceiver-QSFP (J30.5), MC3-Transceiver (MC3.108)
QSFP_1_TX4P: Transceiver-QSFP (J30.6), MC3-Transceiver (MC3.106)
QSFP_2_INT_B: Transceiver-QSFP (R45.1 U8.2), MC2 (MC2.127)
QSFP_2_LP_MODE: Transceiver-QSFP (U7.4), MC2 (MC2.128)
QSFP_2_MODPRS_B: Transceiver-QSFP (U7.1), MC2 (MC2.134)
QSFP_2_MODSEL_B: Transceiver-QSFP (U7.3), MC2 (MC2.130)
QSFP_2_RESET_B: Transceiver-QSFP (U7.2), MC2 (MC2.132)
QSFP_2_RX1N: Transceiver-QSFP (J31.18), MC3-Transceiver (MC3.55)
QSFP_2_RX1P: Transceiver-QSFP (J31.17), MC3-Transceiver (MC3.53)
QSFP_2_RX2N: Transceiver-QSFP (J31.21), MC3-Transceiver (MC3.59)
QSFP_2_RX2P: Transceiver-QSFP (J31.22), MC3-Transceiver (MC3.57)
QSFP_2_RX3N: Transceiver-QSFP (J31.15), MC3-Transceiver (MC3.63)
QSFP_2_RX3P: Transceiver-QSFP (J31.14), MC3-Transceiver (MC3.61)
QSFP_2_RX4N: Transceiver-QSFP (J31.24), MC3-Transceiver (MC3.67)
QSFP_2_RX4P: Transceiver-QSFP (J31.25), MC3-Transceiver (MC3.65)
QSFP_2_SCL: Transceiver-QSFP (R57.1 U10.2), MC2 (MC2.131)
QSFP_2_SDA: Transceiver-QSFP (R58.1 U10.3), MC2 (MC2.133)
QSFP_2_TX1N: Transceiver-QSFP (J31.37), MC3-Transceiver (MC3.68)
QSFP_2_TX1P: Transceiver-QSFP (J31.36), MC3-Transceiver (MC3.66)
QSFP_2_TX2N: Transceiver-QSFP (J31.2), MC3-Transceiver (MC3.64)
QSFP_2_TX2P: Transceiver-QSFP (J31.3), MC3-Transceiver (MC3.62)
QSFP_2_TX3N: Transceiver-QSFP (J31.34), MC3-Transceiver (MC3.60)
QSFP_2_TX3P: Transceiver-QSFP (J31.33), MC3-Transceiver (MC3.58)
QSFP_2_TX4N: Transceiver-QSFP (J31.5), MC3-Transceiver (MC3.56)
QSFP_2_TX4P: Transceiver-QSFP (J31.6), MC3-Transceiver (MC3.54)

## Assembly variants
Default: not fitted MC1A MC1B MC1C MC1D MC2A MC2B R4 R5 R6 R15 SO1 SO2 SO4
